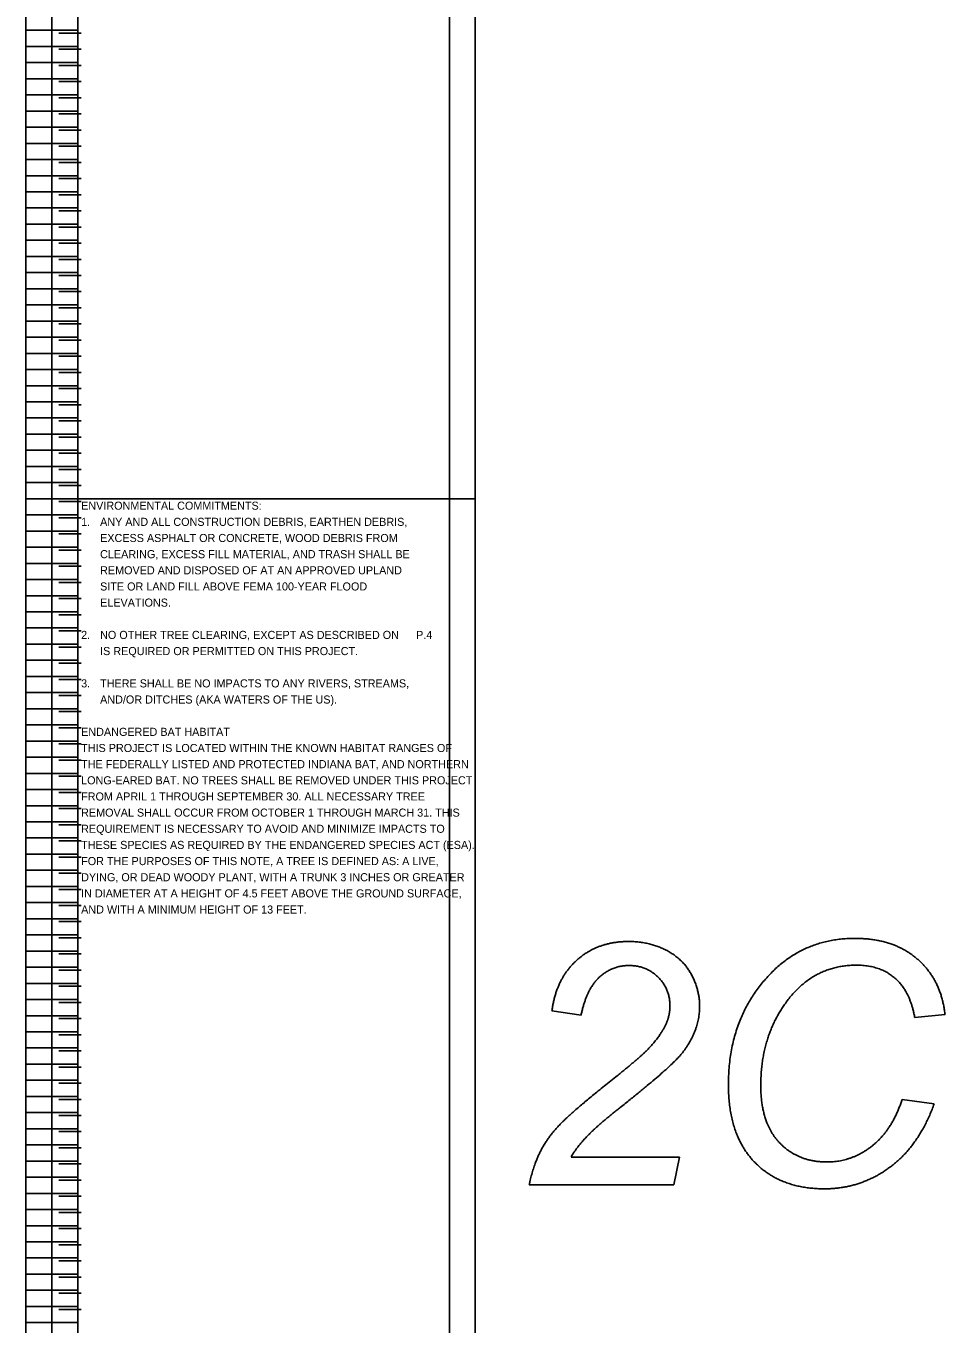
# Model space of a CAD drawing. Extents: x 12316 to 12541, y 1124 to 1850.
# Drawn here: x 12521.92 to 12537.85, y 1714.53 to 1737.03 of the extents above; entities that cross this region are included whole.
import ezdxf

# ---------------------------------------------------------------- set-up
doc = ezdxf.new("R2010")
doc.units = 0
for name, color, linetype in [('SC_Scratch1', 7, 'Continuous'), ('SH_Data', 7, 'Continuous'), ('SH_Text', 7, 'Continuous')]:
    doc.layers.add(name, color=color, linetype=linetype)

msp = doc.modelspace()

# ---------------------------------------------------------------- linework, layer by layer
at = {"layer": 'SC_Scratch1'}
for p, q in [((12522.819, 1769.381), (12522.819, 1728.831)), ((12521.919, 1728.831), (12521.919, 1748.991)), ((12522.819, 1728.831), (12522.819, 1748.991)), ((12521.919, 1736.951), (12522.819, 1736.951)), ((12522.876, 1736.901), (12522.492, 1736.901)), ((12521.919, 1736.671), (12522.819, 1736.671)), ((12522.876, 1736.621), (12522.492, 1736.621)), ((12521.919, 1736.391), (12522.819, 1736.391)), ((12522.876, 1736.341), (12522.492, 1736.341)), ((12521.919, 1736.111), (12522.819, 1736.111)), ((12522.876, 1736.061), (12522.492, 1736.061)), ((12521.919, 1735.831), (12522.819, 1735.831)), ((12522.876, 1735.781), (12522.492, 1735.781)), ((12521.919, 1735.551), (12522.819, 1735.551)), ((12522.876, 1735.501), (12522.492, 1735.501)), ((12521.919, 1735.271), (12522.819, 1735.271)), ((12522.876, 1735.221), (12522.492, 1735.221)), ((12521.919, 1734.991), (12522.819, 1734.991)), ((12522.876, 1734.941), (12522.492, 1734.941)), ((12521.919, 1734.711), (12522.819, 1734.711)), ((12522.876, 1734.661), (12522.492, 1734.661)), ((12521.919, 1734.431), (12522.819, 1734.431)), ((12522.876, 1734.381), (12522.492, 1734.381)), ((12521.919, 1734.151), (12522.819, 1734.151)), ((12522.876, 1734.101), (12522.492, 1734.101)), ((12521.919, 1733.871), (12522.819, 1733.871)), ((12522.876, 1733.821), (12522.492, 1733.821)), ((12521.919, 1733.591), (12522.819, 1733.591)), ((12522.876, 1733.541), (12522.492, 1733.541)), ((12521.919, 1733.311), (12522.819, 1733.311)), ((12522.876, 1733.261), (12522.492, 1733.261)), ((12521.919, 1733.031), (12522.819, 1733.031)), ((12522.876, 1732.981), (12522.492, 1732.981)), ((12521.919, 1732.751), (12522.819, 1732.751)), ((12522.876, 1732.701), (12522.492, 1732.701)), ((12521.919, 1732.471), (12522.819, 1732.471)), ((12522.876, 1732.421), (12522.492, 1732.421)), ((12521.919, 1732.191), (12522.819, 1732.191)), ((12522.876, 1732.141), (12522.492, 1732.141)), ((12521.919, 1731.911), (12522.819, 1731.911)), ((12522.876, 1731.861), (12522.492, 1731.861)), ((12521.919, 1731.631), (12522.819, 1731.631)), ((12522.876, 1731.581), (12522.492, 1731.581)), ((12521.919, 1731.351), (12522.819, 1731.351)), ((12522.876, 1731.301), (12522.492, 1731.301)), ((12521.919, 1731.071), (12522.819, 1731.071)), ((12522.876, 1731.021), (12522.492, 1731.021)), ((12521.919, 1730.791), (12522.819, 1730.791)), ((12522.876, 1730.741), (12522.492, 1730.741)), ((12521.919, 1730.511), (12522.819, 1730.511)), ((12522.876, 1730.461), (12522.492, 1730.461)), ((12521.919, 1730.231), (12522.819, 1730.231)), ((12522.876, 1730.181), (12522.492, 1730.181)), ((12521.919, 1729.951), (12522.819, 1729.951)), ((12522.876, 1729.901), (12522.492, 1729.901)), ((12521.919, 1729.671), (12522.819, 1729.671)), ((12522.876, 1729.621), (12522.492, 1729.621)), ((12521.919, 1729.391), (12522.819, 1729.391)), ((12522.876, 1729.341), (12522.492, 1729.341)), ((12521.919, 1729.111), (12522.819, 1729.111)), ((12522.876, 1729.061), (12522.492, 1729.061)), ((12521.919, 1728.831), (12522.819, 1728.831)), ((12521.919, 1708.671), (12521.919, 1728.831)), ((12521.919, 1728.831), (12522.819, 1728.831)), ((12522.876, 1728.781), (12522.492, 1728.781)), ((12522.819, 1708.671), (12522.819, 1728.831)), ((12522.819, 1728.831), (12522.819, 1708.671)), ((12521.919, 1728.551), (12522.819, 1728.551)), ((12522.876, 1728.501), (12522.492, 1728.501)), ((12521.919, 1728.271), (12522.819, 1728.271)), ((12522.876, 1728.221), (12522.492, 1728.221)), ((12521.919, 1727.991), (12522.819, 1727.991)), ((12522.876, 1727.941), (12522.492, 1727.941)), ((12521.919, 1727.711), (12522.819, 1727.711)), ((12522.876, 1727.661), (12522.492, 1727.661)), ((12521.919, 1727.431), (12522.819, 1727.431)), ((12522.876, 1727.381), (12522.492, 1727.381)), ((12521.919, 1727.151), (12522.819, 1727.151)), ((12522.876, 1727.101), (12522.492, 1727.101)), ((12521.919, 1726.871), (12522.819, 1726.871)), ((12522.876, 1726.821), (12522.492, 1726.821)), ((12521.919, 1726.591), (12522.819, 1726.591)), ((12522.876, 1726.541), (12522.492, 1726.541)), ((12521.919, 1726.311), (12522.819, 1726.311)), ((12522.876, 1726.261), (12522.492, 1726.261)), ((12521.919, 1726.031), (12522.819, 1726.031)), ((12522.876, 1725.981), (12522.492, 1725.981)), ((12521.919, 1725.751), (12522.819, 1725.751)), ((12522.876, 1725.701), (12522.492, 1725.701)), ((12521.919, 1725.471), (12522.819, 1725.471)), ((12522.876, 1725.421), (12522.492, 1725.421)), ((12521.919, 1725.191), (12522.819, 1725.191)), ((12522.876, 1725.141), (12522.492, 1725.141)), ((12521.919, 1724.911), (12522.819, 1724.911)), ((12522.876, 1724.861), (12522.492, 1724.861)), ((12521.919, 1724.631), (12522.819, 1724.631)), ((12522.876, 1724.581), (12522.492, 1724.581)), ((12521.919, 1724.351), (12522.819, 1724.351)), ((12522.876, 1724.301), (12522.492, 1724.301)), ((12521.919, 1724.071), (12522.819, 1724.071)), ((12522.876, 1724.021), (12522.492, 1724.021)), ((12521.919, 1723.791), (12522.819, 1723.791)), ((12522.876, 1723.741), (12522.492, 1723.741)), ((12521.919, 1723.511), (12522.819, 1723.511)), ((12522.876, 1723.461), (12522.492, 1723.461)), ((12521.919, 1723.231), (12522.819, 1723.231)), ((12522.876, 1723.181), (12522.492, 1723.181)), ((12521.919, 1722.951), (12522.819, 1722.951)), ((12522.876, 1722.901), (12522.492, 1722.901)), ((12521.919, 1722.671), (12522.819, 1722.671)), ((12522.876, 1722.621), (12522.492, 1722.621)), ((12521.919, 1722.391), (12522.819, 1722.391)), ((12522.876, 1722.341), (12522.492, 1722.341)), ((12521.919, 1722.111), (12522.819, 1722.111)), ((12522.876, 1722.061), (12522.492, 1722.061)), ((12521.919, 1721.831), (12522.819, 1721.831)), ((12522.876, 1721.781), (12522.492, 1721.781)), ((12521.919, 1721.551), (12522.819, 1721.551)), ((12522.876, 1721.501), (12522.492, 1721.501)), ((12521.919, 1721.271), (12522.819, 1721.271)), ((12522.876, 1721.221), (12522.492, 1721.221)), ((12521.919, 1720.991), (12522.819, 1720.991)), ((12522.876, 1720.941), (12522.492, 1720.941)), ((12521.919, 1720.711), (12522.819, 1720.711)), ((12522.876, 1720.661), (12522.492, 1720.661)), ((12521.919, 1720.431), (12522.819, 1720.431)), ((12522.876, 1720.381), (12522.492, 1720.381)), ((12521.919, 1720.151), (12522.819, 1720.151)), ((12522.876, 1720.101), (12522.492, 1720.101)), ((12531.543, 1719.879), (12531.037, 1719.954)), ((12537.852, 1719.889), (12537.327, 1719.841)), ((12521.919, 1719.871), (12522.819, 1719.871)), ((12522.876, 1719.821), (12522.492, 1719.821)), ((12521.919, 1719.591), (12522.819, 1719.591)), ((12522.876, 1719.541), (12522.492, 1719.541)), ((12521.919, 1719.311), (12522.819, 1719.311)), ((12522.876, 1719.261), (12522.492, 1719.261)), ((12521.919, 1719.031), (12522.819, 1719.031)), ((12522.876, 1718.981), (12522.492, 1718.981)), ((12521.919, 1718.751), (12522.819, 1718.751)), ((12522.876, 1718.701), (12522.492, 1718.701)), ((12521.919, 1718.471), (12522.819, 1718.471)), ((12522.876, 1718.421), (12522.492, 1718.421)), ((12537.107, 1718.42), (12537.664, 1718.343)), ((12521.919, 1718.191), (12522.819, 1718.191)), ((12522.876, 1718.141), (12522.492, 1718.141)), ((12521.919, 1717.911), (12522.819, 1717.911)), ((12522.876, 1717.861), (12522.492, 1717.861)), ((12521.919, 1717.631), (12522.819, 1717.631)), ((12522.876, 1717.581), (12522.492, 1717.581)), ((12521.919, 1717.351), (12522.819, 1717.351)), ((12522.876, 1717.301), (12522.492, 1717.301)), ((12521.919, 1717.071), (12522.819, 1717.071)), ((12522.876, 1717.021), (12522.492, 1717.021)), ((12521.919, 1716.791), (12522.819, 1716.791)), ((12522.876, 1716.741), (12522.492, 1716.741)), ((12521.919, 1716.511), (12522.819, 1716.511)), ((12522.876, 1716.461), (12522.492, 1716.461)), ((12521.919, 1716.231), (12522.819, 1716.231)), ((12522.876, 1716.181), (12522.492, 1716.181)), ((12521.919, 1715.951), (12522.819, 1715.951)), ((12522.876, 1715.901), (12522.492, 1715.901)), ((12521.919, 1715.671), (12522.819, 1715.671)), ((12522.876, 1715.621), (12522.492, 1715.621)), ((12521.919, 1715.391), (12522.819, 1715.391)), ((12522.876, 1715.341), (12522.492, 1715.341)), ((12521.919, 1715.111), (12522.819, 1715.111)), ((12522.876, 1715.061), (12522.492, 1715.061)), ((12521.919, 1714.831), (12522.819, 1714.831)), ((12522.876, 1714.781), (12522.492, 1714.781)), ((12521.919, 1714.551), (12522.819, 1714.551))]:
    msp.add_line(p, q, dxfattribs=at)
for points in [[(12522.369, 1748.991), (12529.709, 1748.991), (12529.709, 1728.831), (12522.369, 1728.831)], [(12522.819, 1748.991), (12529.259, 1748.991), (12529.259, 1728.831), (12522.819, 1728.831)], [(12522.369, 1728.831), (12529.709, 1728.831), (12529.709, 1708.671), (12522.369, 1708.671)], [(12522.819, 1728.831), (12529.259, 1728.831), (12529.259, 1708.671), (12522.819, 1708.671)]]:
    msp.add_lwpolyline(points, close=True, dxfattribs=at)
msp.add_lwpolyline([(12531.369, 1717.418), (12533.249, 1717.418), (12533.149, 1716.941), (12530.643, 1716.941)], dxfattribs=at)
for points in [[(12531.471, 1720.835), (12531.831, 1721.157), (12532.366, 1721.157)], [(12532.366, 1721.157), (12532.724, 1721.157), (12533.015, 1721.008)], [(12534.78, 1720.55), (12535.387, 1721.211), (12536.29, 1721.211)], [(12536.29, 1721.211), (12536.958, 1721.211), (12537.372, 1720.853)], [(12531.037, 1719.954), (12531.111, 1720.512), (12531.471, 1720.835)], [(12533.015, 1721.008), (12533.306, 1720.859), (12533.452, 1720.59)], [(12537.372, 1720.853), (12537.786, 1720.494), (12537.852, 1719.889)], [(12532.374, 1720.741), (12532.079, 1720.741), (12531.858, 1720.536)], [(12532.878, 1720.539), (12532.673, 1720.741), (12532.374, 1720.741)], [(12533.452, 1720.59), (12533.598, 1720.321), (12533.598, 1720.034)], [(12536.316, 1720.747), (12535.545, 1720.747), (12535.069, 1720.063)], [(12536.984, 1720.522), (12536.725, 1720.747), (12536.316, 1720.747)], [(12531.858, 1720.536), (12531.637, 1720.331), (12531.543, 1719.879)], [(12533.083, 1720.048), (12533.083, 1720.337), (12532.878, 1720.539)], [(12534.097, 1718.674), (12534.097, 1719.808), (12534.78, 1720.55)], [(12537.327, 1719.841), (12537.244, 1720.297), (12536.984, 1720.522)], [(12533.017, 1719.73), (12533.083, 1719.876), (12533.083, 1720.048)], [(12533.598, 1720.034), (12533.598, 1719.616), (12533.3, 1719.229)], [(12535.069, 1720.063), (12534.658, 1719.473), (12534.658, 1718.663)], [(12532.704, 1719.292), (12532.919, 1719.516), (12533.017, 1719.73)], [(12532.148, 1718.814), (12532.555, 1719.138), (12532.704, 1719.292)], [(12533.3, 1719.229), (12533.117, 1718.989), (12532.223, 1718.282)], [(12531.242, 1718.051), (12531.477, 1718.279), (12532.148, 1718.814)], [(12534.546, 1717.337), (12534.097, 1717.804), (12534.097, 1718.674)], [(12534.658, 1718.663), (12534.658, 1718.016), (12534.976, 1717.675)], [(12536.593, 1717.618), (12536.946, 1717.902), (12537.107, 1718.42)], [(12537.664, 1718.343), (12537.4, 1717.615), (12536.895, 1717.243)], [(12532.223, 1718.282), (12531.839, 1717.979), (12531.651, 1717.784)], [(12530.865, 1717.57), (12531.007, 1717.824), (12531.242, 1718.051)], [(12531.651, 1717.784), (12531.463, 1717.59), (12531.369, 1717.418)], [(12534.976, 1717.675), (12535.294, 1717.335), (12535.805, 1717.335)], [(12530.643, 1716.941), (12530.724, 1717.316), (12530.865, 1717.57)], [(12535.805, 1717.335), (12536.24, 1717.335), (12536.593, 1717.618)], [(12535.761, 1716.87), (12534.995, 1716.87), (12534.546, 1717.337)], [(12536.895, 1717.243), (12536.39, 1716.87), (12535.761, 1716.87)]]:
    msp.add_open_spline(points, degree=2, dxfattribs=at)

# ---------------------------------------------------------------- texts
at = {"layer": 'SH_Data'}
for s, p in [('ENDANGERED BAT HABITAT', (12522.876, 1724.721)), ('THIS PROJECT IS LOCATED WITHIN THE KNOWN HABITAT RANGES OF ', (12522.876, 1724.441)), ('THE FEDERALLY LISTED AND PROTECTED INDIANA BAT, AND NORTHERN ', (12522.876, 1724.161)), ('LONG-EARED BAT. NO TREES SHALL BE REMOVED UNDER THIS PROJECT ', (12522.876, 1723.881)), ('FROM APRIL 1 THROUGH SEPTEMBER 30. ALL NECESSARY TREE ', (12522.876, 1723.601)), ('REMOVAL SHALL OCCUR FROM OCTOBER 1 THROUGH MARCH 31. THIS ', (12522.876, 1723.321)), ('REQUIREMENT IS NECESSARY TO AVOID AND MINIMIZE IMPACTS TO ', (12522.876, 1723.041)), ('THESE SPECIES AS REQUIRED BY THE ENDANGERED SPECIES ACT (ESA). ', (12522.876, 1722.761)), ('FOR THE PURPOSES OF THIS NOTE, A TREE IS DEFINED AS: A LIVE, ', (12522.876, 1722.481)), ('DYING, OR DEAD WOODY PLANT, WITH A TRUNK 3 INCHES OR GREATER ', (12522.876, 1722.201)), ('IN DIAMETER AT A HEIGHT OF 4.5 FEET ABOVE THE GROUND SURFACE, ', (12522.876, 1721.921)), ('AND WITH A MINIMUM HEIGHT OF 13 FEET.', (12522.876, 1721.641))]:
    msp.add_text(s, height=0.14, dxfattribs=at).set_placement(p)
at = {"layer": 'SH_Text'}
for s, p in [('ENVIRONMENTAL COMMITMENTS:', (12522.876, 1728.641)), ('1.', (12522.876, 1728.361)), ('ANY AND ALL CONSTRUCTION DEBRIS, EARTHEN DEBRIS, ', (12523.205, 1728.361)), ('EXCESS ASPHALT OR CONCRETE, WOOD DEBRIS FROM ', (12523.205, 1728.081)), ('CLEARING, EXCESS FILL MATERIAL, AND TRASH SHALL BE ', (12523.205, 1727.801)), ('REMOVED AND DISPOSED OF AT AN APPROVED UPLAND ', (12523.205, 1727.521)), ('SITE OR LAND FILL ABOVE FEMA 100-YEAR FLOOD ', (12523.205, 1727.241)), ('ELEVATIONS.', (12523.205, 1726.961)), ('2.', (12522.876, 1726.401)), ('NO OTHER TREE CLEARING, EXCEPT AS DESCRIBED ON          ', (12523.205, 1726.401)), ('P.4', (12528.683, 1726.401)), ('IS REQUIRED OR PERMITTED ON THIS PROJECT. ', (12523.205, 1726.121)), ('3.', (12522.876, 1725.561)), ('THERE SHALL BE NO IMPACTS TO ANY RIVERS, STREAMS, ', (12523.205, 1725.561)), ('AND/OR DITCHES (AKA WATERS OF THE US).', (12523.205, 1725.281))]:
    msp.add_text(s, height=0.14, dxfattribs=at).set_placement(p)

doc.saveas('drawing.dxf')
